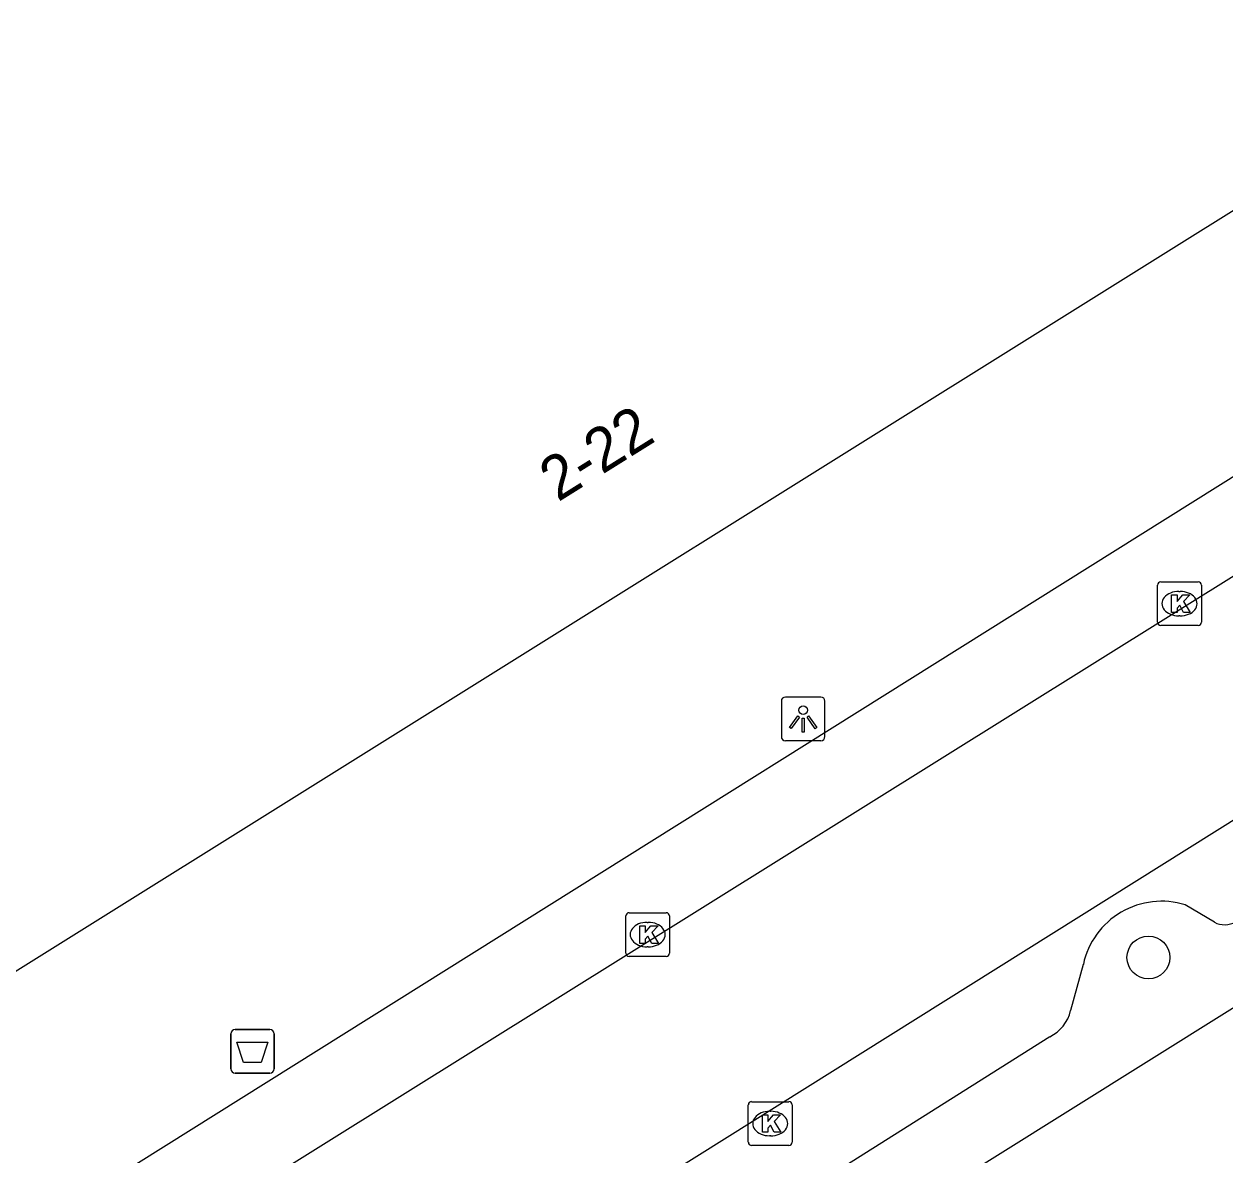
# Model space of a CAD drawing. Extents: x 159353 to 160616, y 385893 to 387321.
# Drawn here: x 159867.44 to 159894.89, y 386171.14 to 386197 of the extents above; entities that cross this region are included whole.
import ezdxf

# ---------------------------------------------------------------- set-up
doc = ezdxf.new("R2010")
doc.units = 0
for name, color, linetype in [('IMGEO_Afvalbak', 7, 'Continuous'), ('IMGEO_Boom', 7, 'Continuous'), ('IMGEO_Kolk', 7, 'Continuous'), ('IMGEO_Lichtpunt', 7, 'Continuous'), ('IMGEO_Pand', 7, 'Continuous'), ('IMGEO_Pand_nummerreeks', 7, 'Continuous'), ('IMGEO_Rijbaan_lokaal_open', 7, 'Continuous'), ('IMGEO_Voetpad_open', 7, 'Continuous')]:
    doc.layers.add(name, color=color, linetype=linetype)

msp = doc.modelspace()

# ---------------------------------------------------------------- linework, layer by layer
at = {"layer": 'IMGEO_Afvalbak'}
for p, q in [((159872.263, 386174.011), (159873.053, 386174.011)), ((159873.053, 386174.011), (159872.263, 386174.011)), ((159872.163, 386173.111), (159872.163, 386173.911)), ((159872.163, 386173.911), (159872.163, 386173.111)), ((159873.153, 386173.911), (159873.153, 386173.111)), ((159873.153, 386173.111), (159873.153, 386173.911)), ((159873.053, 386173.011), (159872.263, 386173.011)), ((159872.263, 386173.011), (159873.053, 386173.011))]:
    msp.add_line(p, q, dxfattribs=at)
msp.add_lwpolyline([(159872.306, 386173.725), (159873.01, 386173.725), (159872.861, 386173.255), (159872.455, 386173.255), (159872.306, 386173.725)], dxfattribs=at)
for centre, start, end in [((159872.263, 386173.911), 90, 180), ((159872.263, 386173.911), 90, 180), ((159873.053, 386173.911), 0, 90), ((159873.053, 386173.911), 360, 90), ((159872.263, 386173.111), 180, 270), ((159872.263, 386173.111), 180, 270), ((159873.053, 386173.111), 270, 0), ((159873.053, 386173.111), 270, 0)]:
    msp.add_arc(centre, 0.1, start, end, dxfattribs=at)
at = {"layer": 'IMGEO_Boom'}
msp.add_circle((159893.135, 386175.659), 0.489, dxfattribs=at)
at = {"layer": 'IMGEO_Kolk'}
for p, q in [((159893.346, 386183.321), (159893.346, 386184.173)), ((159893.421, 386184.247), (159894.273, 386184.247)), ((159894.347, 386184.173), (159894.347, 386183.321)), ((159893.834, 386184.027), (159893.859, 386184.027)), ((159893.857, 386183.467), (159893.832, 386183.467)), ((159894.273, 386183.247), (159893.421, 386183.247)), ((159881.266, 386176.681), (159882.118, 386176.681)), ((159881.191, 386175.755), (159881.191, 386176.607)), ((159881.679, 386176.461), (159881.704, 386176.461)), ((159882.192, 386176.607), (159882.192, 386175.755)), ((159881.702, 386175.901), (159881.677, 386175.901)), ((159882.118, 386175.681), (159881.266, 386175.681)), ((159883.992, 386171.435), (159883.992, 386172.287)), ((159884.067, 386172.361), (159884.919, 386172.361)), ((159884.993, 386172.287), (159884.993, 386171.435)), ((159884.48, 386172.141), (159884.505, 386172.141)), ((159884.503, 386171.581), (159884.478, 386171.581)), ((159884.919, 386171.361), (159884.067, 386171.361))]:
    msp.add_line(p, q, dxfattribs=at)
for points in [[(159893.346, 386183.321), (159893.346, 386184.173)], [(159893.421, 386184.247), (159894.273, 386184.247)], [(159894.347, 386184.173), (159894.347, 386183.321)], [(159893.667, 386183.947), (159893.79, 386183.947), (159893.79, 386183.796), (159893.92, 386183.947), (159894.084, 386183.947), (159893.938, 386183.796), (159894.091, 386183.547), (159893.939, 386183.547), (159893.854, 386183.711), (159893.79, 386183.644), (159893.79, 386183.547), (159893.667, 386183.547), (159893.667, 386183.947)], [(159894.273, 386183.247), (159893.421, 386183.247)], [(159881.266, 386176.681), (159882.118, 386176.681)], [(159881.191, 386175.755), (159881.191, 386176.607)], [(159882.192, 386176.607), (159882.192, 386175.755)], [(159881.512, 386176.381), (159881.635, 386176.381), (159881.635, 386176.23), (159881.765, 386176.381), (159881.929, 386176.381), (159881.783, 386176.23), (159881.936, 386175.981), (159881.784, 386175.981), (159881.699, 386176.145), (159881.635, 386176.078), (159881.635, 386175.981), (159881.512, 386175.981), (159881.512, 386176.381)], [(159882.118, 386175.681), (159881.266, 386175.681)], [(159883.992, 386171.435), (159883.992, 386172.287)], [(159884.067, 386172.361), (159884.919, 386172.361)], [(159884.993, 386172.287), (159884.993, 386171.435)], [(159884.313, 386172.061), (159884.436, 386172.061), (159884.436, 386171.91), (159884.566, 386172.061), (159884.73, 386172.061), (159884.584, 386171.91), (159884.737, 386171.661), (159884.585, 386171.661), (159884.5, 386171.825), (159884.436, 386171.758), (159884.436, 386171.661), (159884.313, 386171.661), (159884.313, 386172.061)], [(159884.919, 386171.361), (159884.067, 386171.361)]]:
    msp.add_lwpolyline(points, dxfattribs=at)
for centre, start, end in [((159893.423, 386184.171), 91.552, 178.448), ((159893.423, 386184.171), 91.552, 178.448), ((159894.271, 386184.171), 1.552, 88.448), ((159894.271, 386184.171), 1.552, 88.448), ((159893.423, 386183.323), 181.552, 268.448), ((159893.423, 386183.323), 181.552, 268.448), ((159894.271, 386183.323), 271.552, 358.448), ((159894.271, 386183.323), 271.552, 358.448), ((159881.268, 386176.605), 91.552, 178.448), ((159881.268, 386176.605), 91.552, 178.448), ((159882.116, 386176.605), 1.552, 88.448), ((159882.116, 386176.605), 1.552, 88.448), ((159881.268, 386175.757), 181.552, 268.448), ((159881.268, 386175.757), 181.552, 268.448), ((159882.116, 386175.757), 271.552, 358.448), ((159882.116, 386175.757), 271.552, 358.448), ((159884.069, 386172.285), 91.552, 178.448), ((159884.069, 386172.285), 91.552, 178.448), ((159884.917, 386172.285), 1.552, 88.448), ((159884.917, 386172.285), 1.552, 88.448), ((159884.069, 386171.437), 181.552, 268.448), ((159884.069, 386171.437), 181.552, 268.448), ((159884.917, 386171.437), 271.552, 358.448), ((159884.917, 386171.437), 271.552, 358.448)]:
    msp.add_arc(centre, 0.0765, start, end, dxfattribs=at)
for centre, major_axis, ratio, start_param, end_param in [((159893.833, 386183.747), (-0.387, 0.002), 0.722429, 4.712389, 7.853982), ((159893.858, 386183.747), (-0.39, 0.002), 0.717154, 1.570796, 4.712389), ((159881.678, 386176.181), (-0.387, 0.002), 0.722429, 4.712389, 7.853982), ((159881.703, 386176.181), (-0.39, 0.002), 0.717154, 1.570796, 4.712389), ((159884.479, 386171.861), (-0.387, 0.002), 0.722429, 4.712389, 7.853982), ((159884.504, 386171.861), (-0.39, 0.002), 0.717154, 1.570796, 4.712389)]:
    msp.add_ellipse(centre, major_axis=major_axis, ratio=ratio, start_param=start_param, end_param=end_param, dxfattribs=at)
at = {"layer": 'IMGEO_Lichtpunt'}
for p, q in [((159885.649, 386181.611), (159884.841, 386181.611)), ((159885.649, 386181.611), (159884.841, 386181.611)), ((159884.747, 386181.516), (159884.747, 386180.709)), ((159884.747, 386181.516), (159884.747, 386180.709)), ((159885.743, 386180.709), (159885.743, 386181.516)), ((159885.743, 386180.709), (159885.743, 386181.516)), ((159884.841, 386180.615), (159885.649, 386180.615)), ((159884.841, 386180.615), (159885.649, 386180.615))]:
    msp.add_line(p, q, dxfattribs=at)
for points in [[(159885.121, 386181.18), (159885.16, 386181.152), (159884.972, 386180.89), (159884.934, 386180.917), (159885.121, 386181.18)], [(159885.223, 386181.132), (159885.27, 386181.132), (159885.27, 386180.81), (159885.223, 386180.81), (159885.223, 386181.132)], [(159885.333, 386181.152), (159885.371, 386181.179), (159885.558, 386180.917), (159885.519, 386180.889), (159885.333, 386181.152)]]:
    msp.add_lwpolyline(points, dxfattribs=at)
msp.add_circle((159885.246, 386181.314), 0.0994, dxfattribs=at)
for centre, start, end in [((159884.841, 386181.516), 90, 180), ((159884.841, 386181.516), 90, 180), ((159885.649, 386181.516), 0, 90), ((159885.649, 386181.516), 0, 90), ((159884.841, 386180.709), 180, 270), ((159884.841, 386180.709), 180, 270), ((159885.649, 386180.709), 270, 0), ((159885.649, 386180.709), 270, 360)]:
    msp.add_arc(centre, 0.0946, start, end, dxfattribs=at)
at = {"layer": 'IMGEO_Pand'}
msp.add_lwpolyline([(159903.24, 386197.844), (159862.318, 386172.259), (159861.631, 386171.83)], dxfattribs=at)
at = {"layer": 'IMGEO_Rijbaan_lokaal_open'}
for points in [[(159907.73, 386192.277), (159863.686, 386164.764)], [(159867.882, 386161.754), (159910.272, 386188.323)]]:
    msp.add_lwpolyline(points, dxfattribs=at)
at = {"layer": 'IMGEO_Voetpad_open'}
for points in [[(159864.259, 386165.766), (159864.604, 386167.306), (159864.784, 386167.671), (159904.106, 386192.314)], [(159894.644, 386176.464), (159893.978, 386176.861)], [(159898.457, 386176.619), (159857.761, 386151.157)], [(159891.648, 386175.501), (159891.358, 386174.442)], [(159890.88, 386173.845), (159885.066, 386170.167)]]:
    msp.add_lwpolyline(points, dxfattribs=at)
for centre, radius, start, end in [((159893.436, 386175.114), 1.829, 72.7553, 167.7881), ((159894.877, 386176.9), 0.494, 241.9425, 300.4296), ((159890.498, 386174.641), 0.883, 295.6405, 346.9931)]:
    msp.add_arc(centre, radius, start, end, dxfattribs=at)

# ---------------------------------------------------------------- texts
at = {"layer": 'IMGEO_Pand_nummerreeks'}
msp.add_text('2-22', height=1, rotation=32.0142, dxfattribs=at).set_placement((159879.64, 386186.06))

doc.saveas('drawing.dxf')
